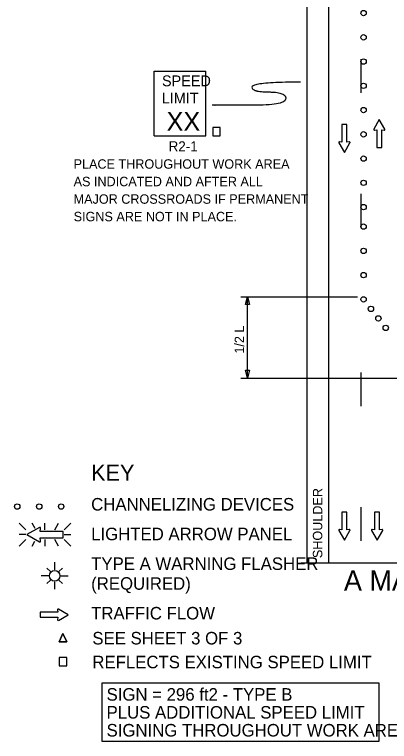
# Model space of a CAD drawing. Extents: x 16730 to 19504, y 5697 to 6911.
# Drawn here: x 16730 to 17009, y 5948 to 6488 of the extents above; entities that cross this region are included whole.
import ezdxf

# ---------------------------------------------------------------- set-up
doc = ezdxf.new("R2010")
doc.units = 0
for name, color, linetype in [('ALI_LEGAL_EX', 7, 'Continuous'), ('MT_SCRATCH_LEVEL_E', 7, 'Continuous'), ('PAVT_EDGE_EX', 7, 'Continuous'), ('TRAFFIC_SIGNS_PR', 7, 'Continuous'), ('TYPICAL_TEXT_DIMEN_EX', 7, 'Continuous'), ('TYPICAL_TEXT_DIMEN_PR', 7, 'Continuous')]:
    doc.layers.add(name, color=color, linetype=linetype)

msp = doc.modelspace()

# ---------------------------------------------------------------- linework, layer by layer
at = {"layer": 'ALI_LEGAL_EX'}
for points in [[(16987.43, 6454.77), (16987.43, 6429.77)], [(16987.43, 6354.77), (16987.43, 6329.77)], [(16987.43, 6222.28), (16987.43, 6197.28)], [(16987.43, 6122.28), (16987.43, 6097.28)]]:
    msp.add_lwpolyline(points, dxfattribs=at)
at = {"layer": 'MT_SCRATCH_LEVEL_E'}
for p, q in [((17001.12, 6409.94), (16997.01, 6402.7)), ((17001.12, 6409.94), (16997.01, 6402.7)), ((17005.26, 6402.7), (17001.12, 6409.94)), ((17005.26, 6402.7), (17001.12, 6409.94)), ((16977.1, 6406.32), (16973.36, 6406.32)), ((16973.36, 6406.32), (16973.36, 6393.06)), ((16977.1, 6406.32), (16973.36, 6406.32)), ((16973.36, 6406.32), (16973.36, 6393.06)), ((16977.1, 6393.06), (16977.1, 6406.32)), ((16977.1, 6393.06), (16977.1, 6406.32)), ((16997.49, 6402.02), (16999.27, 6402.33)), ((16997.49, 6402.02), (16999.27, 6402.33)), ((16999.27, 6402.33), (16999.27, 6389.08)), ((16999.27, 6402.33), (16999.27, 6389.08)), ((17003.01, 6389.08), (17003.01, 6402.33)), ((17003.01, 6402.33), (17004.78, 6402.02)), ((17003.01, 6389.08), (17003.01, 6402.33)), ((17003.01, 6402.33), (17004.78, 6402.02)), ((16973.36, 6393.06), (16971.58, 6393.37)), ((16973.36, 6393.06), (16971.58, 6393.37)), ((16978.88, 6393.37), (16977.1, 6393.06)), ((16978.88, 6393.37), (16977.1, 6393.06)), ((16971.1, 6392.69), (16975.25, 6385.45)), ((16971.1, 6392.69), (16975.25, 6385.45)), ((16975.25, 6385.45), (16979.36, 6392.69)), ((16975.25, 6385.45), (16979.36, 6392.69)), ((16999.27, 6389.08), (17003.01, 6389.08)), ((16999.27, 6389.08), (17003.01, 6389.08)), ((16977.1, 6118.56), (16973.36, 6118.56)), ((16973.36, 6118.56), (16973.36, 6105.31)), ((16977.1, 6118.56), (16973.36, 6118.56)), ((16973.36, 6118.56), (16973.36, 6105.31)), ((16977.1, 6105.31), (16977.1, 6118.56)), ((16977.1, 6105.31), (16977.1, 6118.56)), ((17001.36, 6118.56), (16997.62, 6118.56)), ((16997.62, 6118.56), (16997.62, 6105.31)), ((17001.36, 6118.56), (16997.62, 6118.56)), ((16997.62, 6118.56), (16997.62, 6105.31)), ((17001.36, 6105.31), (17001.36, 6118.56)), ((17001.36, 6105.31), (17001.36, 6118.56)), ((16971.1, 6104.94), (16975.25, 6097.7)), ((16971.1, 6104.94), (16975.25, 6097.7)), ((16973.36, 6105.31), (16971.58, 6105.62)), ((16973.36, 6105.31), (16971.58, 6105.62)), ((16975.25, 6097.7), (16979.36, 6104.94)), ((16975.25, 6097.7), (16979.36, 6104.94)), ((16978.88, 6105.62), (16977.1, 6105.31)), ((16978.88, 6105.62), (16977.1, 6105.31)), ((16995.36, 6104.94), (16999.51, 6097.7)), ((16995.36, 6104.94), (16999.51, 6097.7)), ((16997.62, 6105.31), (16995.84, 6105.62)), ((16997.62, 6105.31), (16995.84, 6105.62)), ((16999.51, 6097.7), (17003.62, 6104.94)), ((16999.51, 6097.7), (17003.62, 6104.94)), ((17003.14, 6105.62), (17001.36, 6105.31)), ((17003.14, 6105.62), (17001.36, 6105.31)), ((16762.68, 6044.26), (16749.42, 6044.26)), ((16749.42, 6044.26), (16749.42, 6040.52)), ((16762.68, 6044.26), (16749.42, 6044.26)), ((16749.42, 6044.26), (16749.42, 6040.52)), ((16762.36, 6046.04), (16762.68, 6044.26)), ((16762.36, 6046.04), (16762.68, 6044.26)), ((16770.29, 6042.41), (16763.05, 6046.52)), ((16770.29, 6042.41), (16763.05, 6046.52)), ((16763.05, 6038.26), (16770.29, 6042.41)), ((16763.05, 6038.26), (16770.29, 6042.41)), ((16749.42, 6040.52), (16762.68, 6040.52)), ((16749.42, 6040.52), (16762.68, 6040.52)), ((16762.68, 6040.52), (16762.36, 6038.74)), ((16762.68, 6040.52), (16762.36, 6038.74))]:
    msp.add_line(p, q, dxfattribs=at)
for centre, start, end in [((16997.41, 6402.48), 150.4248, 279.9638), ((16997.41, 6402.48), 150.4248, 279.9638), ((17004.85, 6402.48), 260.0362, 29.7731), ((17004.85, 6402.48), 260.0362, 29.7731), ((16971.51, 6392.91), 80.0362, 209.7731), ((16971.51, 6392.91), 80.0362, 209.7731), ((16978.96, 6392.91), 330.4248, 99.9638), ((16978.96, 6392.91), 330.4248, 99.9638), ((16971.51, 6105.16), 80.0362, 209.7731), ((16971.51, 6105.16), 80.0362, 209.7731), ((16978.96, 6105.16), 330.4248, 99.9638), ((16978.96, 6105.16), 330.4248, 99.9638), ((16995.77, 6105.16), 80.0362, 209.7731), ((16995.77, 6105.16), 80.0362, 209.7731), ((17003.21, 6105.16), 330.4248, 99.9638), ((17003.21, 6105.16), 330.4248, 99.9638), ((16762.82, 6046.11), 60.4248, 189.9638), ((16762.82, 6046.11), 60.4248, 189.9638), ((16762.82, 6038.67), 170.0362, 299.7731), ((16762.82, 6038.67), 170.0362, 299.7731)]:
    msp.add_arc(centre, 0.463, start, end, dxfattribs=at)
at = {"layer": 'PAVT_EDGE_EX'}
for p, q in [((16947.43, 6911.29), (16947.43, 6081.05)), ((16963.43, 6911.29), (16963.43, 6081.05))]:
    msp.add_line(p, q, dxfattribs=at)
at = {"layer": 'TRAFFIC_SIGNS_PR'}
for p, q in [((16834.12, 6445.79), (16872.52, 6445.79)), ((16834.12, 6397.79), (16834.12, 6445.79)), ((16872.52, 6397.79), (16872.52, 6445.79)), ((16834.12, 6397.79), (16872.52, 6397.79)), ((16733.97, 6110.35), (16738.9, 6105.42)), ((16745.73, 6106.53), (16743.52, 6110.35)), ((16753.05, 6105.42), (16753.05, 6110.35)), ((16760.29, 6105.42), (16763.14, 6110.35)), ((16767.2, 6105.42), (16772.14, 6110.35)), ((16738.9, 6101.86), (16733.97, 6101.86)), ((16767.2, 6101.86), (16772.14, 6101.86)), ((16733.97, 6093.37), (16738.9, 6098.3)), ((16743.48, 6093.37), (16745.59, 6097.03)), ((16753.05, 6098.3), (16753.05, 6093.37)), ((16763.18, 6093.37), (16760.33, 6098.3)), ((16767.2, 6098.3), (16772.14, 6093.37)), ((16760.26, 6075.7), (16760.26, 6081.32)), ((16757.12, 6074.4), (16754.49, 6077.03)), ((16763.39, 6074.4), (16766.02, 6077.03)), ((16756.32, 6071.26), (16750.28, 6071.26)), ((16764.19, 6071.26), (16770.29, 6071.26)), ((16757.12, 6068.12), (16754.49, 6065.49)), ((16760.26, 6061.31), (16760.26, 6066.82)), ((16763.39, 6068.12), (16766.02, 6065.49))]:
    msp.add_line(p, q, dxfattribs=at)
for points in [[(16877.54, 6397.79), (16883.13, 6397.79), (16883.13, 6403.96), (16877.54, 6403.96)], [(16763.6, 6004.5), (16769.19, 6004.5), (16769.19, 6010.67), (16763.6, 6010.67)]]:
    msp.add_lwpolyline(points, close=True, dxfattribs=at)
for points in [[(16748.98, 6107.14), (16739.69, 6101.86), (16748.98, 6096.54)], [(16749.85, 6097.17), (16749.45, 6099.43), (16766.47, 6099.43), (16766.47, 6104.24), (16749.45, 6104.24), (16749.86, 6106.52)], [(16766.39, 6028.38), (16763.6, 6022.21)], [(16763.6, 6022.21), (16766.39, 6028.38)], [(16769.19, 6022.21), (16766.39, 6028.38)], [(16766.39, 6028.38), (16769.19, 6022.21)], [(16763.6, 6022.21), (16769.19, 6022.21)], [(16769.19, 6022.21), (16763.6, 6022.21)]]:
    msp.add_lwpolyline(points, dxfattribs=at)
for centre, radius in [((16989.44, 6488.95), 2), ((16989.44, 6470.95), 2), ((16989.44, 6452.95), 2), ((16989.44, 6434.95), 2), ((16989.44, 6416.95), 2), ((16989.44, 6398.95), 2), ((16989.44, 6380.95), 2), ((16989.44, 6362.95), 2), ((16989.44, 6344.95), 2), ((16989.44, 6330.47), 2), ((16989.44, 6312.47), 2), ((16989.44, 6294.47), 2), ((16989.44, 6276.47), 2), ((16994.92, 6269.41), 2), ((17000.41, 6262.35), 2), ((17005.89, 6255.3), 2), ((16732.48, 6122.7), 2), ((16748.78, 6122.7), 2), ((16765.08, 6122.7), 2), ((16760.26, 6071.26), 3.94)]:
    msp.add_circle(centre, radius, dxfattribs=at)
for centre, radius, start, end in [((16749.27, 6106.61), 0.598, 350.7308, 118.8916), ((16749.27, 6097.06), 0.597, 241.4833, 9.9593)]:
    msp.add_arc(centre, radius, start, end, dxfattribs=at)
at = {"layer": 'TYPICAL_TEXT_DIMEN_EX'}
msp.add_lwpolyline([(16795.41, 5991.77), (17000.78, 5991.77), (17000.78, 5948.37), (16795.41, 5948.37)], close=True, dxfattribs=at)
at = {"layer": 'TYPICAL_TEXT_DIMEN_PR'}
for p, q in [((16898.34, 6278.47), (16984.84, 6278.47)), ((16901.77, 6272.6), (16903.34, 6278.47)), ((16903.34, 6218.03), (16903.34, 6278.47)), ((16903.34, 6278.47), (16904.91, 6272.6)), ((16903.34, 6272.6), (16901.77, 6272.6)), ((16904.91, 6272.6), (16903.34, 6272.6)), ((16903.34, 6218.03), (16901.77, 6223.89)), ((16901.77, 6223.89), (16903.34, 6223.89)), ((16903.34, 6223.89), (16904.91, 6223.89)), ((16904.91, 6223.89), (16903.34, 6218.03)), ((16898.34, 6218.03), (17027.97, 6218.03)), ((16943.13, 6081.05), (17103.73, 6081.05))]:
    msp.add_line(p, q, dxfattribs=at)
msp.add_open_spline([(16942.67, 6437.65), (16906.58, 6437.65), (16906.58, 6430.39), (16931.76, 6430.39), (16931.76, 6420.48), (16882.11, 6420.48), (16877.18, 6420.48)], degree=2, dxfattribs=at)

# ---------------------------------------------------------------- texts
at = {"layer": 'TRAFFIC_SIGNS_PR'}
for s, height, p in [('SPEED', 8, (16839.88, 6434.65)), ('LIMIT', 8, (16839.72, 6421.85)), ('XX', 14.031, (16843.23, 6401.55)), ('R2-1', 7.44, (16844.79, 6386.35)), ('PLACE THROUGHOUT WORK AREA', 7, (16774.31, 6373.43)), ('AS INDICATED AND AFTER ALL', 7, (16774.31, 6360.43)), ('MAJOR CROSSROADS IF PERMANENT', 7, (16774.31, 6347.43)), ('SIGNS ARE NOT IN PLACE.', 7, (16774.31, 6334.43))]:
    msp.add_text(s, height=height, dxfattribs=at).set_placement(p)
at = {"layer": 'TYPICAL_TEXT_DIMEN_EX'}
for s, height, p in [('KEY', 12, (16787.32, 6141.81)), ('CHANNELIZING DEVICES', 9.3, (16787.32, 6119.76)), ('LIGHTED ARROW PANEL', 9.3, (16787.32, 6097.71)), ('TYPE A WARNING FLASHER', 9.3, (16787.32, 6075.66)), ('(REQUIRED)', 9.3, (16787.32, 6060.96)), ('TRAFFIC FLOW', 9.3, (16787.32, 6038.91)), ('SEE SHEET 3 OF 3', 9.3, (16788.21, 6020.37)), ('REFLECTS EXISTING SPEED LIMIT', 9.3, (16788.21, 6002.66)), ('SIGN = 296 ft2 - TYPE B', 9.3, (16798.75, 5978.65)), ('PLUS ADDITIONAL SPEED LIMIT', 9.3, (16798.75, 5965.35)), ('SIGNING THROUGHOUT WORK AREA', 9.3, (16798.75, 5952.05))]:
    msp.add_text(s, height=height, dxfattribs=at).set_placement(p)
at = {"layer": 'TYPICAL_TEXT_DIMEN_PR'}
for s, p in [('1/2 L', (16900.78, 6236.19)), ('SHOULDER', (16958.81, 6084.43))]:
    msp.add_text(s, height=7, rotation=90, dxfattribs=at).set_placement(p)
msp.add_text('A MATCH A', height=15, dxfattribs=at).set_placement((16974.85, 6060.35))

doc.saveas('drawing.dxf')
